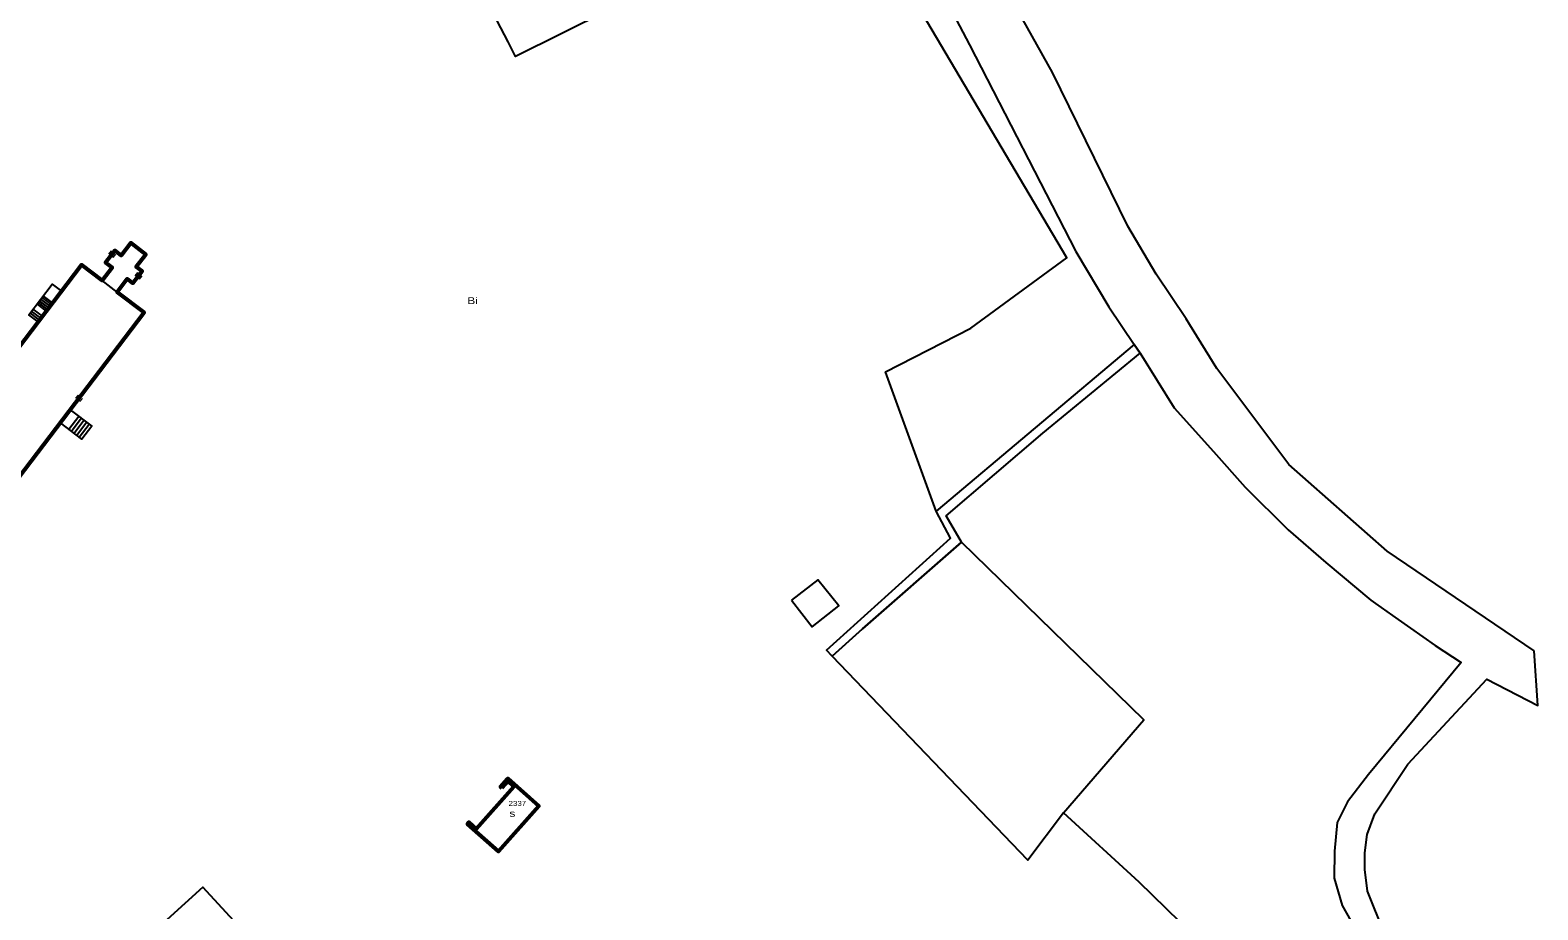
# Model space of a CAD drawing. Extents: x 4641351 to 4644672, y 5357112 to 5362385.
# Drawn here: x 4642892.9 to 4643168.9, y 5358631 to 5358792.2 of the extents above; entities that cross this region are included whole.
import ezdxf
from ezdxf.enums import TextEntityAlignment as Align

# ---------------------------------------------------------------- set-up
doc = ezdxf.new("R2010")
doc.units = 0
doc.header["$LTSCALE"] = 0.5
for name, color, linetype, lineweight in [('15', 7, 'Continuous', 25), ('25', 7, 'Continuous', 25), ('27', 7, 'Continuous', 25), ('3', 7, 'Continuous', 13), ('6', 7, 'Continuous', 25)]:
    doc.layers.add(name, color=color, linetype=linetype, lineweight=lineweight)
doc.layers.add('26', color=7, linetype='Continuous')
doc.layers.add('4', color=7, linetype='Continuous')

msp = doc.modelspace()

# ---------------------------------------------------------------- linework, layer by layer
at = {"layer": '15'}
for p, q in [((4642896.048, 5358741.017), (4642894.336, 5358742.319)), ((4642896.278, 5358741.318), (4642894.566, 5358742.62)), ((4642896.507, 5358741.62), (4642894.795, 5358742.922)), ((4642896.737, 5358741.922), (4642895.025, 5358743.224)), ((4642896.966, 5358742.223), (4642895.254, 5358743.525)), ((4642894.566, 5358739.068), (4642892.854, 5358740.37)), ((4642894.831, 5358739.416), (4642893.12, 5358740.718)), ((4642895.097, 5358739.765), (4642893.385, 5358741.067)), ((4642895.819, 5358740.715), (4642894.107, 5358742.017)), ((4642899.94, 5358719.075), (4642901.735, 5358721.435)), ((4642900.416, 5358718.713), (4642902.211, 5358721.072)), ((4642900.893, 5358718.35), (4642902.688, 5358720.71)), ((4642901.369, 5358717.988), (4642903.164, 5358720.347)), ((4642901.846, 5358717.625), (4642903.641, 5358719.985))]:
    msp.add_line(p, q, dxfattribs=at)
for points in [[(4642894.301, 5358738.719), (4642892.589, 5358740.021), (4642896.878, 5358745.66), (4642898.59, 5358744.358)], [(4642900.184, 5358722.614), (4642904.117, 5358719.622), (4642902.322, 5358717.263), (4642898.389, 5358720.255)]]:
    msp.add_lwpolyline(points, close=True, dxfattribs=at)
at = {"layer": '25'}
for points in [[(4643007.42, 5358800.143), (4642981.731, 5358787.358), (4642980.347, 5358790.024), (4642975.665, 5358799.045)], [(4643103.347, 5358628.863), (4643095.887, 5358636.097), (4643082.025, 5358648.799), (4643075.497, 5358640.165), (4643039.7, 5358677.489), (4643045.24, 5358682.506), (4643063.354, 5358698.391), (4643060.585, 5358703.212), (4643078.258, 5358718.33), (4643096.062, 5358732.987), (4643094.996, 5358734.582), (4643058.723, 5358704.059), (4643049.478, 5358729.586), (4643065.081, 5358737.579), (4643082.671, 5358750.492), (4643053.66, 5358799.583)]]:
    msp.add_lwpolyline(points, dxfattribs=at)
for points in [[(4643032.232, 5358687.76), (4643036.035, 5358682.876), (4643040.941, 5358686.706), (4643037.086, 5358691.499)], [(4642893.44, 5358607.05), (4642931.14, 5358573.61), (4642959.35, 5358597.293), (4642946.467, 5358611.297), (4642924.48, 5358635.21)]]:
    msp.add_lwpolyline(points, close=True, dxfattribs=at)
at = {"layer": '27'}
for points in [[(4643168.251, 5358678.464), (4643141.291, 5358696.751), (4643123.28, 5358712.597), (4643110.133, 5358730.171), (4643105.181, 5358738.177), (4643104.49, 5358739.294), (4643099.027, 5358747.447), (4643093.832, 5358756.27), (4643080.022, 5358784.398), (4643050.533, 5358837.181)], [(4643053.817, 5358810.526), (4643064.817, 5358789.479), (4643084.327, 5358751.639), (4643090.364, 5358741.514), (4643094.996, 5358734.582), (4643096.062, 5358732.987), (4643102.319, 5358722.998), (4643109.491, 5358714.971)], [(4643103.347, 5358628.863), (4643095.887, 5358636.097), (4643082.025, 5358648.799), (4643096.754, 5358665.817), (4643063.354, 5358698.391), (4643045.24, 5358682.506), (4643039.7, 5358677.489), (4643038.64, 5358678.59), (4643061.357, 5358699.15), (4643058.723, 5358704.059), (4643049.478, 5358729.586), (4643065.081, 5358737.579), (4643082.671, 5358750.492), (4643053.66, 5358799.583)], [(4643109.491, 5358714.971), (4643115.304, 5358708.465), (4643123.205, 5358700.646), (4643130.08, 5358694.673), (4643138.313, 5358687.784), (4643139.162, 5358687.179), (4643143.296, 5358684.23), (4643150.118, 5358679.464), (4643154.864, 5358676.356), (4643137.912, 5358655.827), (4643134.019, 5358650.806), (4643132.186, 5358647.051), (4643131.675, 5358641.778), (4643131.59, 5358636.851), (4643133.08, 5358631.827), (4643137.277, 5358624.369)], [(4643140.836, 5358626.721), (4643137.719, 5358634.442), (4643137.24, 5358638.456), (4643137.209, 5358641.496), (4643137.628, 5358644.825), (4643139.079, 5358648.605), (4643145.121, 5358657.729), (4643159.575, 5358673.271), (4643168.9, 5358668.477), (4643168.251, 5358678.464)]]:
    msp.add_lwpolyline(points, dxfattribs=at)
for points in [[(4643032.232, 5358687.76), (4643036.035, 5358682.876), (4643040.941, 5358686.706), (4643037.086, 5358691.499)], [(4642893.44, 5358607.05), (4642931.14, 5358573.61), (4642959.35, 5358597.293), (4642946.467, 5358611.297), (4642924.48, 5358635.21)]]:
    msp.add_lwpolyline(points, close=True, dxfattribs=at)
at = {"layer": '3'}
for p, q in [((4642907.661, 5358751.742), (4642907.207, 5358751.145)), ((4642907.661, 5358751.742), (4642908.003, 5358750.54)), ((4642908.457, 5358751.137), (4642908.003, 5358750.54)), ((4642912.082, 5358747.179), (4642912.536, 5358747.776)), ((4642912.878, 5358746.574), (4642912.536, 5358747.776)), ((4642912.878, 5358746.574), (4642913.332, 5358747.171)), ((4642901.171, 5358724.737), (4642901.625, 5358725.334)), ((4642901.967, 5358724.132), (4642901.625, 5358725.334)), ((4642901.967, 5358724.132), (4642902.421, 5358724.729))]:
    msp.add_line(p, q, dxfattribs=at)
at = {"layer": '3', "lineweight": 53}
msp.add_lwpolyline([(4642856.231, 5358664.839), (4642913.751, 5358740.447), (4642908.807, 5358744.208), (4642910.63, 5358746.604), (4642911.671, 5358745.812), (4642913.334, 5358747.999), (4642912.291, 5358748.792), (4642914.018, 5358751.063), (4642911.263, 5358753.184), (4642909.523, 5358750.896), (4642908.334, 5358751.801), (4642906.67, 5358749.614), (4642907.863, 5358748.707), (4642906.041, 5358746.312), (4642902.263, 5358749.186), (4642877.436, 5358716.548)], dxfattribs=at)
msp.add_lwpolyline([(4642979.242, 5358653.357), (4642978.994, 5358653.577), (4642980.325, 5358655.077), (4642985.981, 5358650.058), (4642978.575, 5358641.721), (4642972.897, 5358646.765), (4642973.184, 5358647.088), (4642974.534, 5358645.889), (4642981.43, 5358653.655), (4642980.355, 5358654.61)], close=True, dxfattribs=at)
at = {"layer": '6'}
msp.add_line((4642908.807, 5358744.208), (4642906.041, 5358746.312), dxfattribs=at)

# ---------------------------------------------------------------- texts
at = {"layer": '26', "width": 1.3}
msp.add_text('Bi', height=1.25, dxfattribs=at).set_placement((4642972.896, 5358741.993))
at = {"layer": '4', "width": 1.2}
msp.add_text('2337', height=0.9, dxfattribs=at).set_placement((4642980.453, 5358650.09))
at = {"layer": '4', "width": 1.3}
msp.add_text('s', height=1.25, dxfattribs=at).set_placement((4642981.147, 5358648.079), align=Align.CENTER)

doc.saveas('drawing.dxf')
